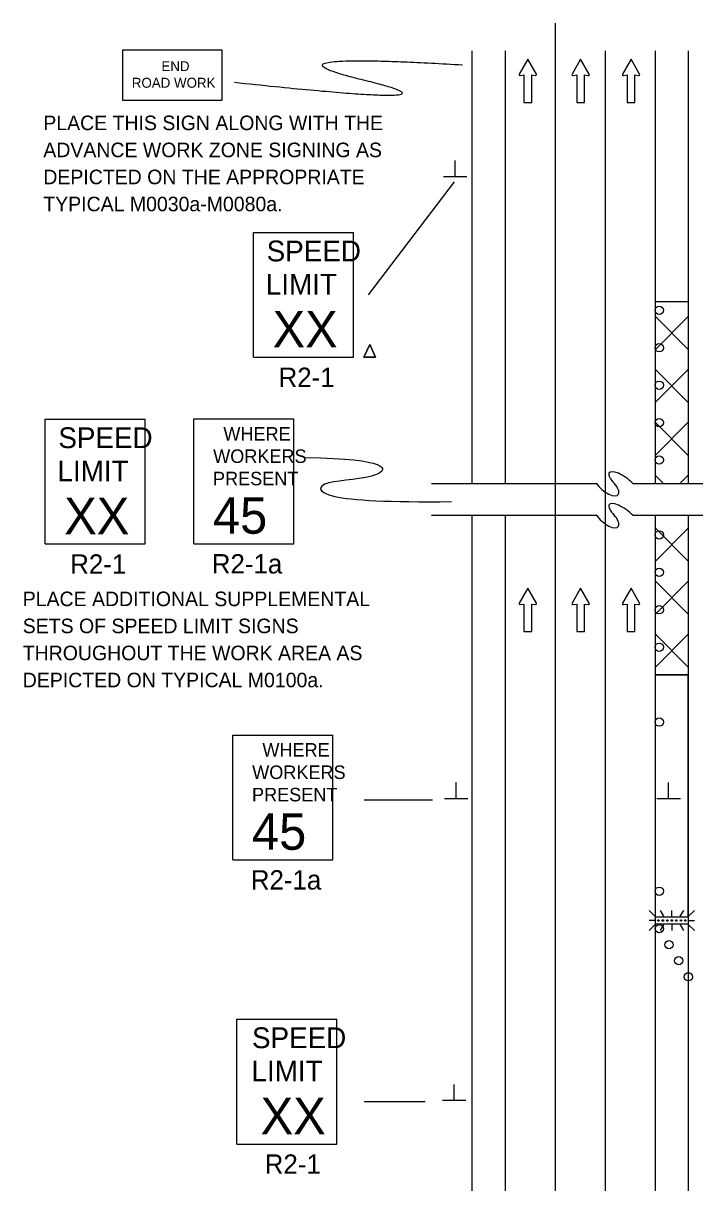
# Model space of a CAD drawing. Extents: x 16730 to 18471, y 6979 to 8225.
# Drawn here: x 16730 to 17053, y 7668 to 8225 of the extents above; entities that cross this region are included whole.
import ezdxf

# ---------------------------------------------------------------- set-up
doc = ezdxf.new("R2010")
doc.units = 0
for name, color, linetype in [('ALI_LEGAL_EX', 7, 'Continuous'), ('MT_SCRATCH_LEVEL_A', 7, 'Continuous'), ('MT_SCRATCH_LEVEL_E', 7, 'Continuous'), ('PAVT_EDGE_EX', 7, 'Continuous'), ('TRAFFIC_SIGNS_PR', 7, 'Continuous'), ('TYPICAL_EX', 7, 'Continuous'), ('TYPICAL_TEXT_DIMEN_PR', 7, 'Continuous')]:
    doc.layers.add(name, color=color, linetype=linetype)

msp = doc.modelspace()

# ---------------------------------------------------------------- linework, layer by layer
at = {"layer": 'ALI_LEGAL_EX'}
for points in [[(16985.65, 8225.29), (16985.65, 8200.29)], [(16985.65, 8216), (16985.65, 8191)], [(16985.65, 8211.96), (16985.65, 8200.29)], [(17009.65, 8211.96), (17009.65, 8200.29)], [(16985.65, 8125.29), (16985.65, 8100.29)], [(16985.65, 8125.29), (16985.65, 8100.29)], [(17009.65, 8125.29), (17009.65, 8100.29)], [(16985.65, 8025.29), (16985.65, 8004.01)], [(17009.65, 8025.29), (17009.65, 8000.29)], [(16985.65, 7961.57), (16985.65, 7936.57)], [(16985.65, 7925.29), (16985.65, 7900.29)], [(17009.65, 7925.29), (17009.65, 7900.29)], [(16985.65, 7825.29), (16985.65, 7800.29)], [(17009.65, 7825.29), (17009.65, 7800.29)], [(16985.65, 7725.29), (16985.65, 7700.29)], [(17009.65, 7725.29), (17009.65, 7700.29)]]:
    msp.add_lwpolyline(points, dxfattribs=at)
at = {"layer": 'MT_SCRATCH_LEVEL_A'}
for p, q in [((17049.65, 8068.41), (17033.65, 8084.41)), ((17033.65, 8068.3), (17049.65, 8084.3)), ((17049.65, 8042.96), (17033.65, 8058.96)), ((17033.65, 8042.85), (17049.65, 8058.85)), ((17049.65, 8017.5), (17033.65, 8033.5)), ((17033.65, 8017.39), (17049.65, 8033.39)), ((17037.68, 8004.02), (17033.65, 8008.05)), ((17045.64, 8003.92), (17049.65, 8007.94)), ((17049.65, 7966.59), (17033.65, 7982.59)), ((17033.65, 7966.48), (17049.65, 7982.48)), ((17049.65, 7941.13), (17033.65, 7957.13)), ((17033.65, 7941.02), (17049.65, 7957.02)), ((17049.65, 7915.68), (17033.65, 7931.68)), ((17033.65, 7915.57), (17049.65, 7931.57))]:
    msp.add_line(p, q, dxfattribs=at)
at = {"layer": 'MT_SCRATCH_LEVEL_E'}
for p, q in [((16972.46, 8208.07), (16968.34, 8200.83)), ((16972.46, 8208.07), (16968.34, 8200.83)), ((16976.6, 8200.83), (16972.46, 8208.07)), ((16976.6, 8200.83), (16972.46, 8208.07)), ((16997.88, 8208.07), (16993.77, 8200.83)), ((16997.88, 8208.07), (16993.77, 8200.83)), ((17002.03, 8200.83), (16997.88, 8208.07)), ((17002.03, 8200.83), (16997.88, 8208.07)), ((17022.09, 8208.07), (17017.98, 8200.83)), ((17022.09, 8208.07), (17017.98, 8200.83)), ((17026.24, 8200.83), (17022.09, 8208.07)), ((17026.24, 8200.83), (17022.09, 8208.07)), ((16968.83, 8200.14), (16970.6, 8200.46)), ((16968.83, 8200.14), (16970.6, 8200.46)), ((16970.6, 8200.46), (16970.6, 8187.2)), ((16970.6, 8200.46), (16970.6, 8187.2)), ((16974.35, 8187.2), (16974.35, 8200.46)), ((16974.35, 8200.46), (16976.12, 8200.14)), ((16974.35, 8187.2), (16974.35, 8200.46)), ((16974.35, 8200.46), (16976.12, 8200.14)), ((16994.25, 8200.14), (16996.03, 8200.46)), ((16994.25, 8200.14), (16996.03, 8200.46)), ((16996.03, 8200.46), (16996.03, 8187.2)), ((16996.03, 8200.46), (16996.03, 8187.2)), ((16999.77, 8187.2), (16999.77, 8200.46)), ((16999.77, 8200.46), (17001.55, 8200.14)), ((16999.77, 8187.2), (16999.77, 8200.46)), ((16999.77, 8200.46), (17001.55, 8200.14)), ((17018.47, 8200.14), (17020.24, 8200.46)), ((17018.47, 8200.14), (17020.24, 8200.46)), ((17020.24, 8200.46), (17020.24, 8187.2)), ((17020.24, 8200.46), (17020.24, 8187.2)), ((17023.98, 8187.2), (17023.98, 8200.46)), ((17023.98, 8200.46), (17025.76, 8200.14)), ((17023.98, 8187.2), (17023.98, 8200.46)), ((17023.98, 8200.46), (17025.76, 8200.14)), ((16970.6, 8187.2), (16974.35, 8187.2)), ((16970.6, 8187.2), (16974.35, 8187.2)), ((16996.03, 8187.2), (16999.77, 8187.2)), ((16996.03, 8187.2), (16999.77, 8187.2)), ((17020.24, 8187.2), (17023.98, 8187.2)), ((17020.24, 8187.2), (17023.98, 8187.2)), ((16972.46, 7953.64), (16968.34, 7946.4)), ((16972.46, 7953.64), (16968.34, 7946.4)), ((16976.6, 7946.4), (16972.46, 7953.64)), ((16976.6, 7946.4), (16972.46, 7953.64)), ((16997.88, 7953.64), (16993.77, 7946.4)), ((16997.88, 7953.64), (16993.77, 7946.4)), ((17002.03, 7946.4), (16997.88, 7953.64)), ((17002.03, 7946.4), (16997.88, 7953.64)), ((17022.09, 7953.64), (17017.98, 7946.4)), ((17022.09, 7953.64), (17017.98, 7946.4)), ((17026.24, 7946.4), (17022.09, 7953.64)), ((17026.24, 7946.4), (17022.09, 7953.64)), ((16968.83, 7945.72), (16970.6, 7946.03)), ((16968.83, 7945.72), (16970.6, 7946.03)), ((16970.6, 7946.03), (16970.6, 7932.78)), ((16970.6, 7946.03), (16970.6, 7932.78)), ((16974.35, 7932.78), (16974.35, 7946.03)), ((16974.35, 7946.03), (16976.12, 7945.72)), ((16974.35, 7932.78), (16974.35, 7946.03)), ((16974.35, 7946.03), (16976.12, 7945.72)), ((16994.25, 7945.72), (16996.03, 7946.03)), ((16994.25, 7945.72), (16996.03, 7946.03)), ((16996.03, 7946.03), (16996.03, 7932.78)), ((16996.03, 7946.03), (16996.03, 7932.78)), ((16999.77, 7932.78), (16999.77, 7946.03)), ((16999.77, 7946.03), (17001.55, 7945.72)), ((16999.77, 7932.78), (16999.77, 7946.03)), ((16999.77, 7946.03), (17001.55, 7945.72)), ((17018.47, 7945.72), (17020.24, 7946.03)), ((17018.47, 7945.72), (17020.24, 7946.03)), ((17020.24, 7946.03), (17020.24, 7932.78)), ((17020.24, 7946.03), (17020.24, 7932.78)), ((17023.98, 7932.78), (17023.98, 7946.03)), ((17023.98, 7946.03), (17025.76, 7945.72)), ((17023.98, 7932.78), (17023.98, 7946.03)), ((17023.98, 7946.03), (17025.76, 7945.72)), ((16970.6, 7932.78), (16974.35, 7932.78)), ((16970.6, 7932.78), (16974.35, 7932.78)), ((16996.03, 7932.78), (16999.77, 7932.78)), ((16996.03, 7932.78), (16999.77, 7932.78)), ((17020.24, 7932.78), (17023.98, 7932.78)), ((17020.24, 7932.78), (17023.98, 7932.78))]:
    msp.add_line(p, q, dxfattribs=at)
for centre, start, end in [((16968.75, 8200.6), 150.4248, 279.9638), ((16968.75, 8200.6), 150.4248, 279.9638), ((16976.19, 8200.6), 260.0362, 29.7731), ((16976.19, 8200.6), 260.0362, 29.7731), ((16994.18, 8200.6), 150.4248, 279.9638), ((16994.18, 8200.6), 150.4248, 279.9638), ((17001.62, 8200.6), 260.0362, 29.7731), ((17001.62, 8200.6), 260.0362, 29.7731), ((17018.39, 8200.6), 150.4248, 279.9638), ((17018.39, 8200.6), 150.4248, 279.9638), ((17025.83, 8200.6), 260.0362, 29.7731), ((17025.83, 8200.6), 260.0362, 29.7731), ((16968.75, 7946.18), 150.4248, 279.9638), ((16968.75, 7946.18), 150.4248, 279.9638), ((16976.19, 7946.18), 260.0362, 29.7731), ((16976.19, 7946.18), 260.0362, 29.7731), ((16994.18, 7946.18), 150.4248, 279.9638), ((16994.18, 7946.18), 150.4248, 279.9638), ((17001.62, 7946.18), 260.0362, 29.7731), ((17001.62, 7946.18), 260.0362, 29.7731), ((17018.39, 7946.18), 150.4248, 279.9638), ((17018.39, 7946.18), 150.4248, 279.9638), ((17025.83, 7946.18), 260.0362, 29.7731), ((17025.83, 7946.18), 260.0362, 29.7731)]:
    msp.add_arc(centre, 0.463, start, end, dxfattribs=at)
at = {"layer": 'PAVT_EDGE_EX'}
for p, q in [((16945.65, 8211.96), (16945.65, 8004.01)), ((16961.65, 8211.96), (16961.65, 8004.01)), ((16985.65, 8211.96), (16985.65, 7344.79)), ((17009.65, 8211.96), (17009.65, 7344.79)), ((17033.65, 8211.96), (17033.65, 8004.01)), ((17049.65, 8211.96), (17049.65, 8004.01)), ((16985.65, 8097.28), (16985.65, 7344.79)), ((17009.65, 8097.28), (17009.65, 7344.79)), ((17033.65, 8091.4), (17049.65, 8091.4)), ((17035.65, 8015.25), (17035.65, 8015.25)), ((16945.65, 7988.69), (16945.65, 7942.5)), ((16961.65, 7988.69), (16961.65, 7942.41)), ((17033.65, 7988.69), (17033.65, 7942.16)), ((17049.65, 7988.69), (17049.65, 7942.41)), ((16945.65, 7942.5), (16945.65, 7379.34)), ((16961.65, 7942.41), (16961.65, 7379.34)), ((17033.65, 7942.16), (17033.65, 7379.34)), ((17049.65, 7942.41), (17049.65, 7379.34)), ((17033.65, 7911.96), (17049.65, 7911.96))]:
    msp.add_line(p, q, dxfattribs=at)
msp.add_lwpolyline([(17049.65, 7795.68), (17049.65, 7911.96), (17033.65, 7911.96), (17033.65, 7795.68)], close=True, dxfattribs=at)
at = {"layer": 'TRAFFIC_SIGNS_PR'}
for p, q in [((16840.65, 8124.69), (16888.65, 8124.69)), ((16840.65, 8064.69), (16840.65, 8124.69)), ((16888.65, 8064.69), (16888.65, 8124.69)), ((16840.65, 8064.69), (16888.65, 8064.69)), ((16740.5, 8034.9), (16788.5, 8034.9)), ((16740.5, 7974.9), (16740.5, 8034.9)), ((16788.5, 7974.9), (16788.5, 8034.9)), ((16812, 8035.01), (16860, 8035.01)), ((16812, 7975.01), (16812, 8035.01)), ((16860, 7975.01), (16860, 8035.01)), ((16740.5, 7974.9), (16788.5, 7974.9)), ((16812, 7975.01), (16860, 7975.01)), ((16830.76, 7883.05), (16878.76, 7883.05)), ((16830.76, 7823.05), (16830.76, 7883.05)), ((16878.76, 7823.05), (16878.76, 7883.05)), ((16830.76, 7823.05), (16878.76, 7823.05)), ((17030.76, 7798.72), (17033.58, 7795.9)), ((17037.85, 7795.9), (17036.22, 7798.72)), ((17041.67, 7795.9), (17041.67, 7798.72)), ((17045.8, 7795.9), (17047.43, 7798.72)), ((17049.75, 7795.9), (17052.57, 7798.72)), ((17033.58, 7793.87), (17030.76, 7793.87)), ((17030.76, 7789.02), (17033.58, 7791.83)), ((17035.22, 7793.87), (17035.22, 7793.87)), ((17036.2, 7789.01), (17037.83, 7791.83)), ((17037.4, 7793.87), (17037.4, 7793.87)), ((17039.57, 7793.87), (17039.57, 7793.87)), ((17041.67, 7791.83), (17041.67, 7789.01)), ((17041.74, 7793.87), (17041.74, 7793.87)), ((17043.92, 7793.87), (17043.92, 7793.87)), ((17047.46, 7789.01), (17045.83, 7791.83)), ((17046.09, 7793.87), (17046.09, 7793.87)), ((17048.26, 7793.87), (17048.26, 7793.87)), ((17049.75, 7793.87), (17052.57, 7793.87)), ((17049.75, 7791.83), (17052.57, 7789.01)), ((16832.67, 7746.41), (16880.67, 7746.41)), ((16832.67, 7686.41), (16832.67, 7746.41)), ((16880.67, 7686.41), (16880.67, 7746.41)), ((16832.67, 7686.41), (16880.67, 7686.41))]:
    msp.add_line(p, q, dxfattribs=at)
for points in [[(16777.61, 8188.32), (16825.61, 8188.32), (16825.61, 8212.32), (16777.61, 8212.32)], [(17049.52, 7792.07), (17033.81, 7792.07), (17033.81, 7795.67), (17049.52, 7795.67)]]:
    msp.add_lwpolyline(points, close=True, dxfattribs=at)
for points in [[(16896.47, 8070.86), (16893.67, 8064.69)], [(16893.67, 8064.69), (16896.47, 8070.86)], [(16899.26, 8064.69), (16896.47, 8070.86)], [(16896.47, 8070.86), (16899.26, 8064.69)], [(16893.67, 8064.69), (16899.26, 8064.69)], [(16899.26, 8064.69), (16893.67, 8064.69)]]:
    msp.add_lwpolyline(points, dxfattribs=at)
for centre, radius in [((17035.65, 8087.25), 2), ((17035.65, 8069.25), 2), ((17035.65, 8051.25), 2), ((17035.65, 8033.25), 2), ((17035.65, 8015.25), 2), ((17035.65, 7979.25), 2), ((17035.65, 7961.25), 2), ((17035.65, 7943.25), 2), ((17035.65, 7925.25), 2), ((17035.65, 7889.25), 2), ((17035.65, 7807.96), 2), ((17035.7, 7789.96), 2), ((17035.24, 7793.87), 0.379), ((17037.39, 7793.87), 0.379), ((17039.57, 7793.87), 0.379), ((17041.74, 7793.87), 0.379), ((17043.91, 7793.87), 0.379), ((17046.09, 7793.87), 0.379), ((17048.26, 7793.87), 0.379), ((17040.35, 7782.25), 2), ((17044.99, 7774.54), 2), ((17049.65, 7766.83), 2)]:
    msp.add_circle(centre, radius, dxfattribs=at)
msp.add_open_spline([(16831.42, 8196.9), (16950.78, 8184.01), (16836.87, 8211.59), (16941.12, 8205.24)], degree=2, dxfattribs=at)
at = {"layer": 'TYPICAL_EX'}
for p, q in [((16926.17, 8004.01), (17005.48, 8004.01)), ((17022.9, 8004.01), (17102.17, 8004.01)), ((16926.17, 7988.69), (17005.48, 7988.69)), ((17022.9, 7988.69), (17102.17, 7988.69))]:
    msp.add_line(p, q, dxfattribs=at)
for centre, major_axis, ratio, start_param, end_param in [((17018.27, 8004.28), (6.66, -4.85), 0.346236, 1.077134, 4.299707), ((17010.23, 8003.47), (-5.67, 4.94), 0.423114, 0.994299, 4.377734), ((17018.27, 7988.96), (6.66, -4.85), 0.346236, 1.077134, 4.299707), ((17010.23, 7988.15), (-5.67, 4.94), 0.423114, 0.994299, 4.377734)]:
    msp.add_ellipse(centre, major_axis=major_axis, ratio=ratio, start_param=start_param, end_param=end_param, dxfattribs=at)
at = {"layer": 'TYPICAL_TEXT_DIMEN_PR'}
for p, q in [((16937.56, 8151.43), (16937.56, 8159.21)), ((16943.19, 8151.43), (16931.94, 8151.43)), ((16895.83, 8094.61), (16937.32, 8148.98)), ((16938.09, 7852.39), (16938.09, 7860.17)), ((17040.18, 7852.39), (17040.18, 7860.17)), ((16893.76, 7851.96), (16926.72, 7851.96)), ((16943.72, 7852.39), (16932.47, 7852.39)), ((17045.81, 7852.39), (17034.56, 7852.39)), ((16937.02, 7707.26), (16937.02, 7715.05)), ((16893.76, 7706.83), (16923.12, 7706.83)), ((16942.65, 7707.26), (16931.4, 7707.26))]:
    msp.add_line(p, q, dxfattribs=at)
msp.add_open_spline([(16865.72, 8016.47), (16905.99, 8015.89), (16905.32, 8005.77), (16871.09, 8005.77), (16871.09, 7996.72), (16905.3, 7994.96), (16935.75, 7995.26)], degree=3, dxfattribs=at)

# ---------------------------------------------------------------- texts
at = {"layer": 'TRAFFIC_SIGNS_PR'}
for s, height, p in [('END', 4.789, (16796.36, 8202.23)), ('ROAD WORK', 4.789, (16782.12, 8194.25)), ('PLACE THIS SIGN ALONG WITH THE', 7, (16739.58, 8173.86)), ('ADVANCE WORK ZONE SIGNING AS', 7, (16739.58, 8160.86)), ('DEPICTED ON THE APPROPRIATE', 7, (16739.58, 8147.86)), ('TYPICAL M0030a-M0080a.', 7, (16739.58, 8134.86)), ('SPEED', 10, (16846.94, 8110.77)), ('LIMIT', 10, (16846.53, 8094.77)), ('XX', 17.538, (16849.79, 8069.39)), ('R2-1', 9.3, (16852.67, 8050.39)), ('SPEED', 10, (16746.79, 8020.98)), ('WHERE', 6.5, (16826.13, 8024.61)), ('WORKERS', 6.5, (16821.23, 8013.86)), ('LIMIT', 10, (16746.38, 8004.98)), ('PRESENT', 6.5, (16821.14, 8003.11)), ('XX', 17.538, (16749.63, 7979.6)), ('45', 17.538, (16821.13, 7979.83)), ('R2-1', 9.3, (16752.51, 7960.6)), ('R2-1a', 9.3, (16820.56, 7960.71)), ('PLACE ADDITIONAL SUPPLEMENTAL', 7, (16729.69, 7945)), ('SETS OF SPEED LIMIT SIGNS', 7, (16729.69, 7932)), ('THROUGHOUT THE WORK AREA AS', 7, (16729.69, 7919)), ('DEPICTED ON TYPICAL M0100a.', 7, (16729.69, 7906)), ('WHERE', 6.5, (16844.89, 7872.65)), ('WORKERS', 6.5, (16839.99, 7861.9)), ('PRESENT', 6.5, (16839.9, 7851.15)), ('45', 17.538, (16839.89, 7827.87)), ('R2-1a', 9.3, (16839.32, 7808.75)), ('SPEED', 10, (16839.88, 7732.49)), ('LIMIT', 10, (16839.67, 7716.49)), ('XX', 17.538, (16844.06, 7691.11)), ('R2-1', 9.3, (16846.01, 7672.11))]:
    msp.add_text(s, height=height, dxfattribs=at).set_placement(p)

doc.saveas('drawing.dxf')
